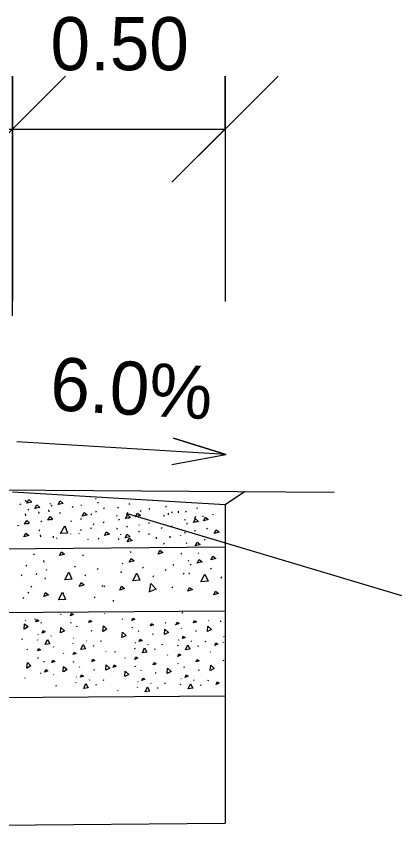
# Model space of a CAD drawing. Extents: x 43.6 to 54.1, y -16.5 to -1.7.
# Drawn here: x 51.143 to 52.049, y -8.475 to -6.556 of the extents above; entities that cross this region are included whole.
import ezdxf

# ---------------------------------------------------------------- set-up
doc = ezdxf.new("R2010")
doc.units = 0
for name, color, linetype in [('KONSTRUKCE_L', 7, 'Continuous'), ('KOTY_REZU', 7, 'Continuous'), ('KOTY_S', 7, 'Continuous'), ('KOTY_T', 7, 'Continuous'), ('Nová vrstva (1)', 7, 'Continuous'), ('TEREN_L', 7, 'Continuous'), ('V_POLYGON', 7, 'Continuous'), ('Vrstva 3', 7, 'Continuous'), ('Vrstva 50', 7, 'Continuous')]:
    doc.layers.add(name, color=color, linetype=linetype)

msp = doc.modelspace()

# ---------------------------------------------------------------- linework, layer by layer
at = {"layer": 'KONSTRUKCE_L'}
for p, q in [((51.6338, -7.7047), (51.6338, -8.1547)), ((49.1338, -7.8247), (51.6338, -7.8047)), ((49.1338, -7.9747), (51.6338, -7.9547)), ((49.1338, -8.1747), (51.6338, -8.1547))]:
    msp.add_line(p, q, dxfattribs=at)
at = {"layer": 'KOTY_REZU'}
for points in [[(49.1338, -7.2046), (49.1338, -6.6965), (49.1338, -6.8215), (49.2588, -6.6965), (49.0088, -6.9465), (49.1338, -6.8215), (51.1338, -6.8215), (51.1338, -6.6965), (51.1338, -6.8215), (51.2588, -6.6965), (51.0088, -6.9465), (51.1338, -6.8215), (51.1338, -7.227)], [(51.1338, -7.2607), (51.1338, -6.6965), (51.1338, -6.8215), (51.2588, -6.6965), (51.0088, -6.9465), (51.1338, -6.8215), (51.6338, -6.8215), (51.6338, -6.6965), (51.6338, -6.8215), (51.7588, -6.6965), (51.5088, -6.9465), (51.6338, -6.8215), (51.6338, -7.227)]]:
    msp.add_lwpolyline(points, dxfattribs=at)
at = {"layer": 'KOTY_S'}
msp.add_lwpolyline([(51.5089, -7.6107), (51.6355, -7.587), (51.5126, -7.5484), (51.6355, -7.587), (51.1439, -7.5571)], dxfattribs=at)
at = {"layer": 'Nová vrstva (1)'}
for p in [(51.6338, -8.1547), (49.1362, -8.4746)]:
    msp.add_line(p, (51.6338, -8.4547), dxfattribs=at)
at = {"layer": 'TEREN_L'}
msp.add_line((46.2067, -7.6389), (51.8901, -7.6757), dxfattribs=at)
at = {"layer": 'V_POLYGON'}
for p, q in [((51.1338, -7.6747), (51.6338, -7.7047)), ((51.6338, -7.7047), (51.6794, -7.6743))]:
    msp.add_line(p, q, dxfattribs=at)
at = {"layer": 'Vrstva 3'}
msp.add_line((52.0492, -7.92), (51.4044, -7.7264), dxfattribs=at)
at = {"layer": 'Vrstva 50'}
for p, q in [((51.3293, -7.6903), (51.3306, -7.6924)), ((51.1516, -7.7033), (51.1529, -7.7055)), ((51.2216, -7.7021), (51.223, -7.7043)), ((51.225, -7.7064), (51.2263, -7.7086)), ((51.2752, -7.7121), (51.2769, -7.709)), ((51.295, -7.7052), (51.2964, -7.7074)), ((51.3342, -7.6995), (51.3354, -7.7018)), ((51.3486, -7.7152), (51.3503, -7.7121)), ((51.3813, -7.7113), (51.3827, -7.7136)), ((51.4076, -7.7026), (51.4088, -7.7049)), ((51.4939, -7.7088), (51.4952, -7.7109)), ((51.5673, -7.7119), (51.5686, -7.7141)), ((51.1703, -7.7159), (51.1716, -7.7181)), ((51.2456, -7.726), (51.2472, -7.7229)), ((51.3191, -7.7291), (51.3206, -7.726)), ((51.3302, -7.7227), (51.3318, -7.7196)), ((51.3786, -7.7303), (51.3799, -7.7325)), ((51.4019, -7.726), (51.4032, -7.7281)), ((51.4036, -7.7258), (51.4052, -7.7227)), ((51.4349, -7.7213), (51.4366, -7.7182)), ((51.4548, -7.7144), (51.4561, -7.7167)), ((51.4899, -7.732), (51.4915, -7.7289)), ((51.5084, -7.7244), (51.5101, -7.7213)), ((51.5411, -7.7206), (51.5424, -7.7228)), ((51.5633, -7.7351), (51.5649, -7.732)), ((51.1695, -7.7485), (51.1708, -7.7507)), ((51.2009, -7.7434), (51.2022, -7.7455)), ((51.2243, -7.739), (51.2255, -7.7412)), ((51.2709, -7.7421), (51.2723, -7.7444)), ((51.2942, -7.7378), (51.2956, -7.74)), ((51.3245, -7.7522), (51.3262, -7.7491)), ((51.3478, -7.7478), (51.3495, -7.7447)), ((51.3835, -7.7396), (51.3847, -7.7418)), ((51.4068, -7.7352), (51.4081, -7.7375)), ((51.4307, -7.7514), (51.432, -7.7537)), ((51.454, -7.747), (51.4553, -7.7493)), ((51.5383, -7.7395), (51.5396, -7.7418)), ((51.5432, -7.7488), (51.5445, -7.751)), ((51.5617, -7.7351), (51.5629, -7.7374)), ((51.5665, -7.7445), (51.5678, -7.7466)), ((51.1462, -7.7529), (51.1475, -7.755)), ((51.197, -7.7666), (51.1985, -7.7635)), ((51.295, -7.7661), (51.2965, -7.763)), ((51.3183, -7.7617), (51.3199, -7.7586)), ((51.3795, -7.7628), (51.3811, -7.7597)), ((51.4028, -7.7584), (51.4044, -7.7553)), ((51.4306, -7.7673), (51.4319, -7.7695)), ((51.4843, -7.7614), (51.486, -7.7583)), ((51.5076, -7.757), (51.5093, -7.7539)), ((51.5392, -7.772), (51.5408, -7.7689)), ((51.5625, -7.7677), (51.5641, -7.7646)), ((51.5904, -7.7606), (51.5918, -7.7628)), ((51.2709, -7.7746), (51.2703, -7.7738)), ((51.291, -7.773), (51.2903, -7.7742)), ((51.3358, -7.7841), (51.3371, -7.7864)), ((51.3825, -7.7849), (51.3838, -7.7871)), ((51.4547, -7.7753), (51.4563, -7.7722)), ((51.5291, -7.7777), (51.5286, -7.779)), ((51.489, -7.7955), (51.4903, -7.7977)), ((51.5423, -7.7941), (51.5435, -7.7963)), ((51.1837, -7.8209), (51.1852, -7.8231)), ((51.2984, -7.823), (51.2998, -7.8252)), ((51.4107, -7.8157), (51.4121, -7.8179)), ((51.5299, -7.8192), (51.5314, -7.8214)), ((51.5707, -7.8182), (51.572, -7.8203)), ((51.3921, -7.8425), (51.3935, -7.8447)), ((51.5114, -7.846), (51.5128, -7.8483)), ((51.5469, -7.8359), (51.5482, -7.8381)), ((51.5521, -7.845), (51.5535, -7.8471)), ((51.1652, -7.8477), (51.1666, -7.8499)), ((51.2135, -7.8575), (51.2149, -7.8596)), ((51.2798, -7.8498), (51.2813, -7.852)), ((51.3338, -7.8576), (51.3353, -7.8544)), ((51.3892, -7.8659), (51.3906, -7.8627)), ((51.4398, -7.8523), (51.4413, -7.8545)), ((51.4938, -7.86), (51.4953, -7.8569)), ((51.5364, -7.869), (51.5378, -7.8658)), ((51.5491, -7.8684), (51.5506, -7.8652)), ((51.5998, -7.8548), (51.6012, -7.857)), ((51.1552, -7.8725), (51.1567, -7.8693)), ((51.1902, -7.8706), (51.1916, -7.8674)), ((51.2105, -7.8808), (51.212, -7.8776)), ((51.3048, -7.8727), (51.3063, -7.8696)), ((51.4648, -7.8752), (51.4663, -7.8721)), ((51.6248, -7.8777), (51.6262, -7.8745)), ((51.1771, -7.8971), (51.1786, -7.8993)), ((51.3444, -7.8954), (51.3459, -7.8976)), ((51.3488, -7.8962), (51.3502, -7.8983)), ((51.5088, -7.8987), (51.5102, -7.9008)), ((51.1586, -7.9239), (51.16, -7.9261)), ((51.1702, -7.9111), (51.1716, -7.9132)), ((51.3258, -7.9222), (51.3273, -7.9245)), ((51.3704, -7.9298), (51.3707, -7.933)), ((51.2467, -7.9623), (51.2476, -7.9635)), ((51.3507, -7.961), (51.3515, -7.9623)), ((51.5331, -7.9601), (51.5345, -7.9569)), ((51.1638, -7.9764), (51.1647, -7.9777)), ((51.1869, -7.9732), (51.1873, -7.9751)), ((51.2015, -7.984), (51.2024, -7.9819)), ((51.2706, -7.9819), (51.2709, -7.9838)), ((51.3914, -7.9734), (51.3923, -7.9747)), ((51.5949, -7.9773), (51.5958, -7.9787)), ((51.623, -7.9785), (51.6234, -7.9805)), ((51.2851, -7.9927), (51.286, -7.9906)), ((51.3197, -8.0029), (51.3205, -8.0008)), ((51.4153, -7.993), (51.4156, -7.995)), ((51.4934, -7.9823), (51.4942, -7.9837)), ((51.5167, -7.986), (51.517, -7.988)), ((51.5312, -7.9968), (51.5321, -7.9948)), ((51.1564, -8.022), (51.1573, -8.0199)), ((51.1937, -8.0094), (51.1945, -8.0107)), ((51.2239, -8.013), (51.2249, -8.0142)), ((51.2773, -8.0181), (51.2782, -8.0194)), ((51.4298, -8.0039), (51.4307, -8.0018)), ((51.4642, -8.0105), (51.4649, -8.0084)), ((51.5656, -8.0035), (51.5663, -8.0014)), ((51.6298, -8.0149), (51.6307, -8.0161)), ((51.193, -8.0242), (51.1937, -8.0221)), ((51.2305, -8.0407), (51.2313, -8.0387)), ((51.2766, -8.0329), (51.2774, -8.0308)), ((51.3077, -8.0253), (51.3087, -8.0265)), ((51.3244, -8.0382), (51.3252, -8.0361)), ((51.3416, -8.0271), (51.3425, -8.0251)), ((51.422, -8.0293), (51.4229, -8.0306)), ((51.4522, -8.0329), (51.4532, -8.0341)), ((51.4861, -8.0348), (51.487, -8.0328)), ((51.5227, -8.037), (51.5234, -8.035)), ((51.5234, -8.0222), (51.5243, -8.0236)), ((51.5536, -8.0259), (51.5546, -8.0271)), ((51.5703, -8.0388), (51.5711, -8.0368)), ((51.5875, -8.0278), (51.5884, -8.0258)), ((51.6291, -8.0295), (51.6298, -8.0275)), ((51.1679, -8.0451), (51.1689, -8.0464)), ((51.2532, -8.0538), (51.2542, -8.0552)), ((51.3532, -8.0504), (51.3541, -8.0516)), ((51.3752, -8.0519), (51.376, -8.0498)), ((51.4213, -8.044), (51.4221, -8.042)), ((51.4689, -8.0459), (51.4697, -8.0438)), ((51.4976, -8.058), (51.4986, -8.0592)), ((51.599, -8.051), (51.6, -8.0522)), ((51.1934, -8.0648), (51.1938, -8.0668)), ((51.2081, -8.0755), (51.2088, -8.0735)), ((51.277, -8.0735), (51.2774, -8.0755)), ((51.3979, -8.065), (51.3989, -8.0663)), ((51.5231, -8.0777), (51.5235, -8.0797)), ((51.6295, -8.0702), (51.6299, -8.0722)), ((51.2919, -8.0878), (51.2927, -8.0858)), ((51.3262, -8.0946), (51.3269, -8.0925)), ((51.4217, -8.0847), (51.4221, -8.0867)), ((51.4364, -8.0954), (51.4371, -8.0934)), ((51.5378, -8.0884), (51.5385, -8.0863)), ((51.5721, -8.0952), (51.5728, -8.0932)), ((51.1629, -8.1137), (51.1637, -8.1116)), ((51.2001, -8.1012), (51.2011, -8.1023)), ((51.2303, -8.1047), (51.2313, -8.1059)), ((51.2837, -8.1099), (51.2847, -8.111)), ((51.4707, -8.1023), (51.4714, -8.1002)), ((51.5298, -8.114), (51.5308, -8.1151)), ((51.2369, -8.1323), (51.2377, -8.1302)), ((51.283, -8.1245), (51.2839, -8.1225)), ((51.3142, -8.1169), (51.3151, -8.1182)), ((51.3309, -8.1297), (51.3316, -8.1277)), ((51.3482, -8.1189), (51.3489, -8.1168)), ((51.4277, -8.1357), (51.4286, -8.1337)), ((51.4284, -8.121), (51.4294, -8.1222)), ((51.4586, -8.1246), (51.4596, -8.1258)), ((51.4754, -8.1374), (51.4761, -8.1354)), ((51.4927, -8.1265), (51.4934, -8.1245)), ((51.5291, -8.1287), (51.53, -8.1266)), ((51.56, -8.1175), (51.561, -8.1188)), ((51.5768, -8.1304), (51.5775, -8.1283)), ((51.5941, -8.1195), (51.5948, -8.1174)), ((51.3816, -8.1435), (51.3824, -8.1414))]:
    msp.add_line(p, q, dxfattribs=at)
for points in [[(51.168, -7.7018), (51.1728, -7.6932), (51.1796, -7.6989), (51.168, -7.7018)], [(51.1662, -7.6986), (51.1656, -7.6944)], [(51.1867, -7.7144), (51.1915, -7.7058), (51.1983, -7.7115), (51.1867, -7.7144)], [(51.2415, -7.7049), (51.2463, -7.6963), (51.253, -7.702), (51.2415, -7.7049)], [(51.1654, -7.7312), (51.1648, -7.727)], [(51.1968, -7.7261), (51.1962, -7.7219)], [(51.2201, -7.7217), (51.2195, -7.7175)], [(51.2978, -7.732), (51.3026, -7.7234), (51.3094, -7.7292), (51.2978, -7.732)], [(51.3999, -7.738), (51.4047, -7.7294), (51.4115, -7.7352), (51.3999, -7.738)], [(51.4232, -7.7337), (51.428, -7.725), (51.4348, -7.7309), (51.4232, -7.7337)], [(51.5012, -7.7287), (51.5007, -7.7249)], [(51.5245, -7.7243), (51.524, -7.7205)], [(51.5825, -7.7337), (51.5822, -7.7315)], [(51.6058, -7.7293), (51.6056, -7.7272)], [(51.1626, -7.7513), (51.1674, -7.7427), (51.1742, -7.7484), (51.1626, -7.7513)], [(51.2174, -7.7418), (51.2222, -7.7332), (51.2289, -7.7389), (51.2174, -7.7418)], [(51.5596, -7.7473), (51.5644, -7.7387), (51.5712, -7.7445), (51.5596, -7.7473)], [(51.5829, -7.7429), (51.5878, -7.7343), (51.5945, -7.7401), (51.5829, -7.7429)], [(51.2465, -7.7729), (51.2571, -7.7553), (51.2636, -7.7724), (51.2469, -7.7729)], [(51.3506, -7.7774), (51.3554, -7.7688), (51.3622, -7.7746), (51.3506, -7.7774)], [(51.6081, -7.7728), (51.6129, -7.7642), (51.6197, -7.77), (51.6081, -7.7728)], [(51.1607, -7.7805), (51.1656, -7.7719), (51.1723, -7.7777), (51.1607, -7.7805)], [(51.2007, -7.7807), (51.2001, -7.7764)], [(51.2306, -7.7831), (51.2301, -7.7793)], [(51.2385, -7.785), (51.2382, -7.7829)], [(51.3119, -7.7881), (51.3116, -7.786)], [(51.3889, -7.7761), (51.3887, -7.7744)], [(51.3989, -7.7834), (51.4038, -7.7746), (51.4105, -7.7805), (51.3989, -7.7834)], [(51.4038, -7.7926), (51.4086, -7.784), (51.4154, -7.7898), (51.4038, -7.7926)], [(51.4728, -7.7854), (51.4723, -7.7816)], [(51.5051, -7.7832), (51.5046, -7.7795)], [(51.5864, -7.7883), (51.5862, -7.7861)], [(51.5635, -7.8019), (51.5684, -7.7932), (51.5751, -7.7991), (51.5635, -7.8019)], [(51.2448, -7.825), (51.2493, -7.8162), (51.2563, -7.8216), (51.2448, -7.825)], [(51.4764, -7.8212), (51.4808, -7.8124), (51.4878, -7.8178), (51.4764, -7.8212)], [(51.6005, -7.8353), (51.605, -7.8265), (51.612, -7.8319), (51.6005, -7.8353)], [(51.2087, -7.8404), (51.2079, -7.8362)], [(51.4085, -7.8403), (51.4129, -7.8315), (51.4199, -7.837), (51.4085, -7.8403)], [(51.5685, -7.8428), (51.5729, -7.834), (51.5799, -7.8395), (51.5685, -7.8428)], [(51.2567, -7.8816), (51.2666, -7.8636), (51.2738, -7.8804), (51.2571, -7.8816)], [(51.4166, -7.8841), (51.4266, -7.8661), (51.4338, -7.8829), (51.417, -7.8841)], [(51.5766, -7.8866), (51.5865, -7.8686), (51.5938, -7.8853), (51.577, -7.8866)], [(51.2909, -7.8974), (51.2953, -7.8886), (51.3023, -7.894), (51.2909, -7.8974)], [(51.3861, -7.906), (51.3904, -7.8972), (51.3974, -7.9026), (51.3861, -7.906)], [(51.4561, -7.9107), (51.4593, -7.8903), (51.4718, -7.9037), (51.4565, -7.9105)], [(51.5461, -7.9085), (51.5504, -7.8997), (51.5574, -7.9051), (51.5461, -7.9085)], [(51.2075, -7.9209), (51.2118, -7.9121), (51.2188, -7.9176), (51.2075, -7.9209)], [(51.2419, -7.9292), (51.2518, -7.9112), (51.259, -7.928), (51.2423, -7.9292)], [(51.6072, -7.9173), (51.6117, -7.9085), (51.6187, -7.9139), (51.6072, -7.9173)], [(51.2703, -7.9664), (51.2726, -7.9607), (51.2773, -7.9636), (51.2703, -7.9664)], [(51.1889, -7.981), (51.1913, -7.9754), (51.196, -7.9784), (51.1889, -7.981)], [(51.3139, -7.9827), (51.3161, -7.977), (51.3208, -7.9801), (51.3139, -7.9827)], [(51.415, -7.9775), (51.4173, -7.9718), (51.422, -7.9747), (51.415, -7.9775)], [(51.5185, -7.987), (51.5209, -7.9814), (51.5256, -7.9844), (51.5185, -7.987)], [(51.5598, -7.9833), (51.562, -7.9777), (51.5667, -7.9806), (51.5598, -7.9833)], [(51.1616, -7.9981), (51.1625, -7.9853), (51.171, -7.9929), (51.1617, -7.998)], [(51.2468, -8.0068), (51.2477, -7.9941), (51.2563, -8.0017), (51.247, -8.0068)], [(51.3468, -8.0033), (51.3477, -7.9905), (51.3562, -7.9981), (51.347, -8.0032)], [(51.4584, -7.9904), (51.4606, -7.9847), (51.4653, -7.9877), (51.4584, -7.9904)], [(51.4913, -8.0109), (51.4922, -7.9981), (51.5007, -8.0058), (51.4915, -8.0108)], [(51.5927, -8.0039), (51.5936, -7.9911), (51.6021, -7.9987), (51.5929, -8.0038)], [(51.2037, -8.0072), (51.2059, -8.0015), (51.2106, -8.0045), (51.2037, -8.0072)], [(51.3915, -8.0179), (51.3924, -8.0052), (51.401, -8.0129), (51.3917, -8.0179)], [(51.5334, -8.02), (51.5357, -8.0144), (51.5403, -8.0174), (51.5334, -8.02)], [(51.2112, -8.034), (51.2163, -8.0222), (51.2217, -8.0324), (51.2114, -8.034)], [(51.295, -8.0462), (51.3001, -8.0345), (51.3055, -8.0447), (51.2952, -8.0462)], [(51.432, -8.0271), (51.4343, -8.0214), (51.4389, -8.0244), (51.432, -8.0271)], [(51.5409, -8.0469), (51.546, -8.0351), (51.5514, -8.0453), (51.5411, -8.0469)], [(51.6095, -8.0362), (51.6119, -8.0304), (51.6166, -8.0335), (51.6095, -8.0362)], [(51.1932, -8.0493), (51.1954, -8.0435), (51.2001, -8.0466), (51.1932, -8.0493)], [(51.2768, -8.058), (51.279, -8.0523), (51.2838, -8.0553), (51.2768, -8.058)], [(51.4395, -8.0539), (51.4446, -8.0421), (51.45, -8.0523), (51.4397, -8.0539)], [(51.5229, -8.0622), (51.5251, -8.0564), (51.5299, -8.0595), (51.5229, -8.0622)], [(51.1681, -8.0897), (51.169, -8.0769), (51.1775, -8.0846), (51.1683, -8.0896)], [(51.2264, -8.0769), (51.2287, -8.0711), (51.2333, -8.0742), (51.2264, -8.0769)], [(51.3203, -8.0743), (51.3226, -8.0686), (51.3273, -8.0716), (51.3203, -8.0743)], [(51.4215, -8.0692), (51.4237, -8.0634), (51.4285, -8.0665), (51.4215, -8.0692)], [(51.4648, -8.082), (51.4671, -8.0763), (51.4718, -8.0793), (51.4648, -8.082)], [(51.5662, -8.075), (51.5685, -8.0692), (51.5731, -8.0723), (51.5662, -8.075)], [(51.2101, -8.0989), (51.2124, -8.0931), (51.2171, -8.0962), (51.2101, -8.0989)], [(51.2534, -8.0984), (51.2543, -8.0856), (51.2627, -8.0933), (51.2536, -8.0983)], [(51.3533, -8.0949), (51.3543, -8.0822), (51.3627, -8.0898), (51.3535, -8.0949)], [(51.3711, -8.0881), (51.3734, -8.0823), (51.378, -8.0854), (51.3711, -8.0881)], [(51.3981, -8.1096), (51.399, -8.0968), (51.4074, -8.1044), (51.3983, -8.1095)], [(51.4978, -8.1026), (51.4987, -8.0898), (51.5072, -8.0974), (51.498, -8.1025)], [(51.5992, -8.0956), (51.6001, -8.0828), (51.6086, -8.0904), (51.5994, -8.0955)], [(51.2939, -8.111), (51.2962, -8.1054), (51.3009, -8.1083), (51.2939, -8.111)], [(51.4384, -8.1187), (51.4407, -8.113), (51.4454, -8.116), (51.4384, -8.1187)], [(51.5398, -8.1117), (51.5421, -8.1059), (51.5468, -8.109), (51.5398, -8.1117)], [(51.3014, -8.1379), (51.3066, -8.1262), (51.312, -8.1362), (51.3017, -8.1379)], [(51.4459, -8.1455), (51.4511, -8.1339), (51.4565, -8.1439), (51.4462, -8.1455)], [(51.5473, -8.1385), (51.5525, -8.1269), (51.5579, -8.1369), (51.5476, -8.1384)], [(51.6128, -8.1279), (51.615, -8.1223), (51.6197, -8.1253), (51.6128, -8.1279)]]:
    msp.add_lwpolyline(points, dxfattribs=at)

# ---------------------------------------------------------------- texts
at = {"layer": 'KOTY_REZU'}
msp.add_text('0.50', height=0.125, rotation=360, dxfattribs=at).set_placement((51.2234, -6.6828))
at = {"layer": 'KOTY_T'}
msp.add_text('6.0%', height=0.125, rotation=356.5664, dxfattribs=at).set_placement((51.2202, -7.4821))

doc.saveas('drawing.dxf')
